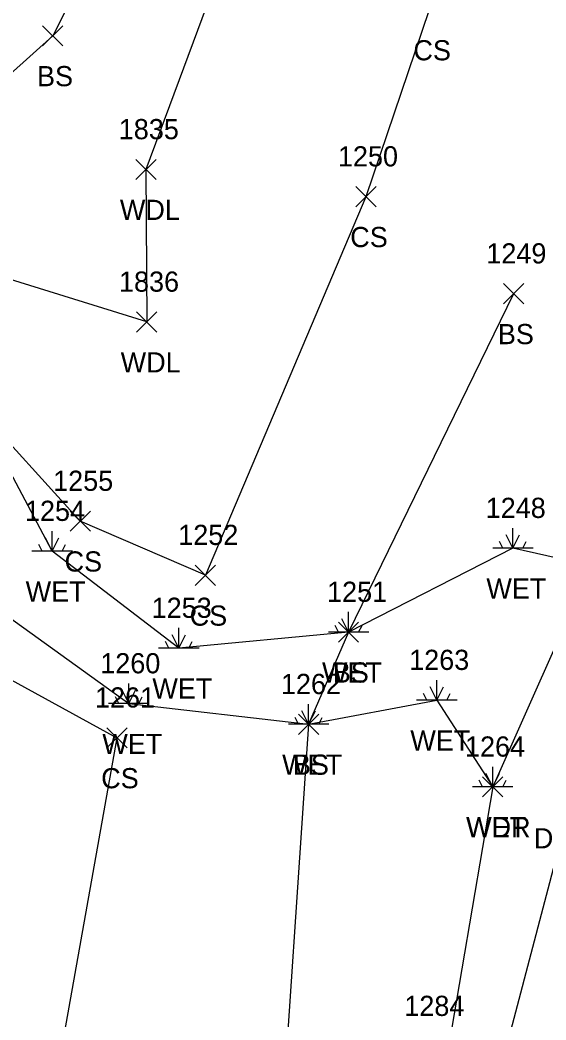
# Model space of a CAD drawing. Extents: x 1551995 to 1555700, y 777276 to 783130.
# Drawn here: x 1554843.1 to 1554895.2, y 778019 to 778118.1 of the extents above; entities that cross this region are included whole.
import ezdxf

# ---------------------------------------------------------------- set-up
doc = ezdxf.new("R2010")
doc.units = 0
for name, color, linetype in [('D_A', 7, 'Continuous'), ('DD', 7, 'Continuous'), ('L_A', 7, 'Continuous'), ('L_I', 7, 'Continuous'), ('L_TIC', 7, 'Continuous'), ('LAWA', 7, 'Continuous'), ('LELB', 7, 'Continuous'), ('LWET', 7, 'Continuous'), ('M_I', 7, 'Continuous')]:
    doc.layers.add(name, color=color, linetype=linetype)

msp = doc.modelspace()

# ---------------------------------------------------------------- linework, layer by layer
at = {"layer": 'DD'}
msp.add_lwpolyline([(1554922.059, 778109.964), (1554914.415, 778091.958), (1554910.403, 778079.818), (1554897.71, 778040.992), (1554886.569, 777998.503), (1554878.331, 777965.3), (1554870.216, 777919.722), (1554862.183, 777878.393), (1554853.394, 777826.983), (1554841.815, 777777.5)], dxfattribs=at)
at = {"layer": 'L_TIC'}
for points in [[(1554845.304, 778115.527), (1554847.304, 778117.527)], [(1554847.304, 778115.527), (1554845.304, 778117.527)], [(1554854.538, 778102.274), (1554856.538, 778104.274)], [(1554856.538, 778102.274), (1554854.538, 778104.274)], [(1554876.326, 778099.58), (1554878.326, 778101.58)], [(1554878.326, 778099.58), (1554876.326, 778101.58)], [(1554890.946, 778089.962), (1554892.946, 778091.962)], [(1554892.946, 778089.962), (1554890.946, 778091.962)], [(1554854.616, 778087.162), (1554856.616, 778089.162)], [(1554856.616, 778087.162), (1554854.616, 778089.162)], [(1554848.037, 778067.426), (1554850.037, 778069.426)], [(1554850.037, 778067.426), (1554848.037, 778069.426)], [(1554860.426, 778062.061), (1554862.426, 778064.061)], [(1554862.426, 778062.061), (1554860.426, 778064.061)], [(1554874.598, 778056.423), (1554876.598, 778058.423)], [(1554876.598, 778056.423), (1554874.598, 778058.423)], [(1554870.644, 778047.288), (1554872.644, 778049.288)], [(1554872.644, 778047.288), (1554870.644, 778049.288)], [(1554851.664, 778045.949), (1554853.664, 778047.949)], [(1554853.664, 778045.949), (1554851.664, 778047.949)], [(1554888.875, 778041.086), (1554890.875, 778043.086)], [(1554890.875, 778041.086), (1554888.875, 778043.086)]]:
    msp.add_lwpolyline(points, dxfattribs=at)
at = {"layer": 'LAWA'}
for points in [[(1554935.431, 778396.621), (1554932.573, 778365.344), (1554927.798, 778334.859), (1554903.785, 778283.497), (1554902.475, 778219.435), (1554891.484, 778177.555), (1554886.356, 778149.248), (1554864.384, 778127.135), (1554855.538, 778103.274), (1554855.616, 778088.162), (1554832.422, 778095.389), (1554813.643, 778080.716)], [(1555000.959, 778294.871), (1554977.329, 778249.83), (1554953.65, 778203.431), (1554934.128, 778158.372), (1554921.739, 778129.694), (1554915.004, 778109.124), (1554905.48, 778082.177), (1554899.619, 778064.005), (1554889.875, 778042.086), (1554882.71, 778000.014), (1554871.693, 777971.466), (1554868.372, 777961.536), (1554861.965, 777920.449), (1554858.528, 777878.75), (1554855.375, 777850.348), (1554848.666, 777827.396), (1554836.715, 777779.634)]]:
    msp.add_lwpolyline(points, dxfattribs=at)
at = {"layer": 'LELB'}
for points in [[(1554968.281, 778312.044), (1554950.001, 778266.534), (1554926.493, 778220.19), (1554908.964, 778174.418), (1554896.479, 778148.261), (1554883.583, 778119.092), (1554877.326, 778100.58), (1554861.426, 778063.061), (1554849.037, 778068.426), (1554838.512, 778079.969)], [(1554800.406, 778253.928), (1554822.718, 778192.195), (1554838.053, 778187.794), (1554853.047, 778176.969), (1554852.09, 778152.192), (1554855.338, 778134.523), (1554846.304, 778116.527), (1554831.672, 778103.381), (1554813.355, 778099.277)], [(1554891.946, 778090.962), (1554875.598, 778057.423), (1554871.644, 778048.288), (1554868.644, 778003.687), (1554860.044, 777985)], [(1554828.477, 778068.893), (1554831.986, 778058.266), (1554852.664, 778046.949), (1554846.704, 778013.579), (1554831.58, 778026.931)]]:
    msp.add_lwpolyline(points, dxfattribs=at)
at = {"layer": 'LWET'}
for p, q in [((1554891.872, 778065.739), (1554891.872, 778067.739)), ((1554846.247, 778065.446), (1554845.58, 778066.779)), ((1554846.247, 778065.446), (1554846.247, 778067.446)), ((1554846.247, 778065.446), (1554846.914, 778066.779)), ((1554891.872, 778065.739), (1554891.205, 778067.072)), ((1554891.872, 778065.739), (1554892.538, 778067.072)), ((1554845.247, 778065.446), (1554844.914, 778066.112)), ((1554847.247, 778065.446), (1554847.58, 778066.112)), ((1554893.872, 778065.739), (1554889.872, 778065.739)), ((1554890.872, 778065.739), (1554890.538, 778066.405)), ((1554892.872, 778065.739), (1554893.205, 778066.405)), ((1554848.247, 778065.446), (1554844.247, 778065.446)), ((1554875.598, 778057.423), (1554874.932, 778058.756)), ((1554875.598, 778057.423), (1554875.598, 778059.423)), ((1554875.598, 778057.423), (1554876.265, 778058.756)), ((1554858.793, 778055.838), (1554858.793, 778057.838)), ((1554874.598, 778057.423), (1554874.265, 778058.09)), ((1554876.598, 778057.423), (1554876.932, 778058.09)), ((1554858.793, 778055.838), (1554858.127, 778057.171)), ((1554858.793, 778055.838), (1554859.46, 778057.171)), ((1554877.598, 778057.423), (1554873.598, 778057.423)), ((1554860.793, 778055.838), (1554856.793, 778055.838)), ((1554857.793, 778055.838), (1554857.46, 778056.504)), ((1554859.793, 778055.838), (1554860.127, 778056.504)), ((1554884.34, 778050.676), (1554884.34, 778052.676)), ((1554853.838, 778050.339), (1554853.171, 778051.672)), ((1554853.838, 778050.339), (1554853.838, 778052.339)), ((1554853.838, 778050.339), (1554854.505, 778051.672)), ((1554884.34, 778050.676), (1554883.673, 778052.009)), ((1554884.34, 778050.676), (1554885.007, 778052.009)), ((1554852.838, 778050.339), (1554852.505, 778051.006)), ((1554854.838, 778050.339), (1554855.171, 778051.006)), ((1554886.34, 778050.676), (1554882.34, 778050.676)), ((1554883.34, 778050.676), (1554883.007, 778051.342)), ((1554885.34, 778050.676), (1554885.673, 778051.342)), ((1554855.838, 778050.339), (1554851.838, 778050.339)), ((1554871.644, 778048.288), (1554871.644, 778050.288)), ((1554870.644, 778048.288), (1554870.311, 778048.955)), ((1554871.644, 778048.288), (1554870.977, 778049.621)), ((1554871.644, 778048.288), (1554872.311, 778049.621)), ((1554872.644, 778048.288), (1554872.977, 778048.955)), ((1554873.644, 778048.288), (1554869.644, 778048.288)), ((1554889.875, 778042.086), (1554889.875, 778044.086)), ((1554888.875, 778042.086), (1554888.541, 778042.752)), ((1554889.875, 778042.086), (1554889.208, 778043.419)), ((1554889.875, 778042.086), (1554890.541, 778043.419)), ((1554890.875, 778042.086), (1554891.208, 778042.752)), ((1554891.875, 778042.086), (1554887.875, 778042.086))]:
    msp.add_line(p, q, dxfattribs=at)
msp.add_lwpolyline([(1554899.619, 778064.005), (1554891.872, 778065.739), (1554875.598, 778057.423), (1554858.793, 778055.838), (1554846.247, 778065.446), (1554838.512, 778079.969), (1554828.477, 778068.893), (1554835.848, 778063.304), (1554853.838, 778050.339), (1554871.644, 778048.288), (1554884.34, 778050.676), (1554889.875, 778042.086)], dxfattribs=at)

# ---------------------------------------------------------------- texts
at = {"layer": 'D_A'}
msp.add_text('DITCH', height=2, dxfattribs=at).set_placement((1554893.946, 778035.992))
at = {"layer": 'L_A'}
for s, p in [('CS', (1554882.024, 778114.092)), ('BS', (1554844.745, 778111.527)), ('WDL', (1554852.956, 778098.274)), ('CS', (1554875.767, 778095.58)), ('BS', (1554890.386, 778085.962)), ('WDL', (1554853.033, 778083.162)), ('CS', (1554847.478, 778063.426)), ('WET', (1554889.25, 778060.739)), ('WET', (1554843.625, 778060.446)), ('CS', (1554859.867, 778058.061)), ('WET', (1554872.976, 778052.423)), ('BS', (1554874.039, 778052.423)), ('WET', (1554856.171, 778050.838)), ('WET', (1554851.216, 778045.339)), ('WET', (1554881.718, 778045.676)), ('WET', (1554869.022, 778043.288)), ('BS', (1554870.085, 778043.288)), ('CS', (1554851.105, 778041.949)), ('WDR', (1554887.237, 778037.086)), ('WET', (1554887.253, 778037.086))]:
    msp.add_text(s, height=2, dxfattribs=at).set_placement(p)
at = {"layer": 'L_I'}
for s, p in [('1835', (1554852.845, 778106.274)), ('1250', (1554874.547, 778103.58)), ('1249', (1554889.245, 778093.962)), ('1836', (1554852.868, 778091.162)), ('1255', (1554846.344, 778071.426)), ('1248', (1554889.179, 778068.739)), ('1254', (1554843.554, 778068.446)), ('1252', (1554858.733, 778066.061)), ('1251', (1554873.472, 778060.423)), ('1251', (1554873.472, 778060.423)), ('1253', (1554856.1, 778058.838)), ('1263', (1554881.6, 778053.676)), ('1260', (1554851.011, 778053.339)), ('1262', (1554868.904, 778051.288)), ('1262', (1554868.904, 778051.288)), ('1261', (1554850.491, 778049.949)), ('1264', (1554887.134, 778045.086)), ('1264', (1554887.134, 778045.086))]:
    msp.add_text(s, height=2, dxfattribs=at).set_placement(p)
at = {"layer": 'M_I'}
msp.add_text('1284', height=2, dxfattribs=at).set_placement((1554881.12, 778019.384))

doc.saveas('drawing.dxf')
